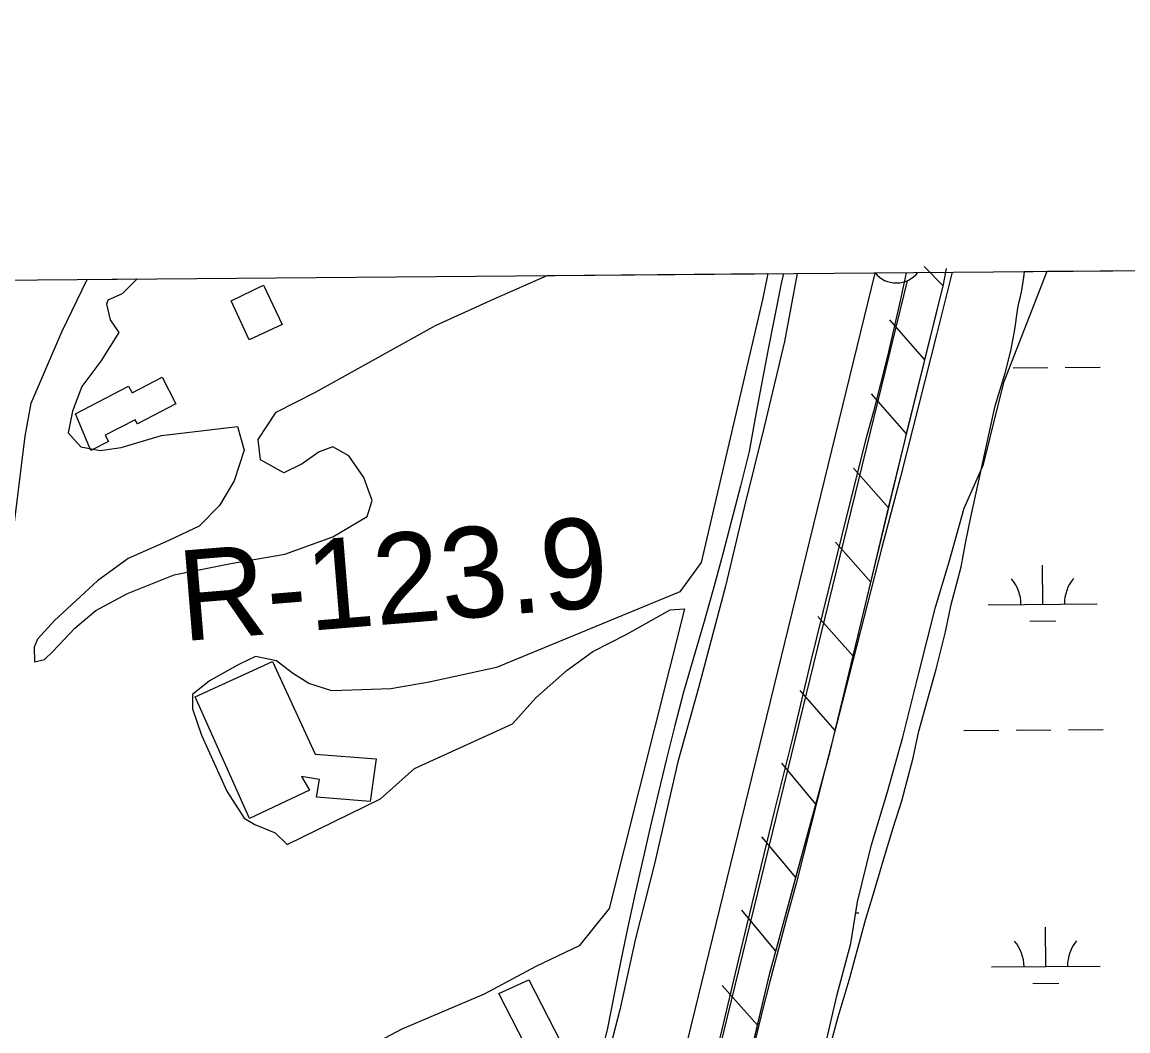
# Model space of a CAD drawing. Extents: x 3567028 to 3605064, y 510945 to 536587.
# Drawn here: x 3574682 to 3575698, y 533872 to 534798 of the extents above; entities that cross this region are included whole.
import ezdxf

# ---------------------------------------------------------------- set-up
doc = ezdxf.new("R2010")
doc.units = 0
for name, color, linetype in [('V-BLDG-OTLN', 7, 'Continuous'), ('V-FLOD-BASE', 7, 'Continuous'), ('V-GRID-FRAM', 7, 'Continuous'), ('V-LEVE-TOET', 7, 'Continuous'), ('V-RIVR-RANG-IDEN', 7, 'Continuous'), ('V-RRAP-FSHR', 7, 'Continuous'), ('V-SITE-VEGE', 7, 'Continuous'), ('V-SURV-LINE', 7, 'Continuous'), ('V-TOPO-SHOR', 7, 'Continuous'), ('V-WETL-SWMP', 7, 'Continuous')]:
    doc.layers.add(name, color=color, linetype=linetype)

msp = doc.modelspace()

# ---------------------------------------------------------------- linework, layer by layer
at = {"layer": 'V-BLDG-OTLN'}
for points in [[(3574874.162, 534542.454), (3574904.149, 534556.995), (3574921.025, 534520.903), (3574890.8310000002, 534506.786)], [(3574731.222, 534438.68), (3574780.088, 534464.14), (3574783.287, 534458.027), (3574810.785, 534472.306), (3574823.446, 534447.912), (3574788.1890000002, 534429.611), (3574786.225, 534433.402), (3574758.67, 534419.111), (3574761.586, 534413.4990000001), (3574745.548, 534405.178)], [(3574841.298, 534178.807), (3574912.3680000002, 534211.304), (3574951.431, 534126.218), (3575007.409, 534122.12), (3575001.915, 534082.715), (3574952.668, 534086.9230000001), (3574955.364, 534103.047), (3574939.035, 534105.7440000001), (3574946.213, 534093.157), (3574890.995, 534067.174)], [(3575120.199, 533906.402), (3575147.677, 533919.188), (3575183.103, 533849.871), (3575156.182, 533836.107)]]:
    msp.add_lwpolyline(points, close=True, dxfattribs=at)
at = {"layer": 'V-FLOD-BASE'}
msp.add_lwpolyline([(3575494.3409218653, 534568.5458403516), (3575494.278, 534568.24), (3575488.751, 534542.659), (3575482.969, 534517.134), (3575476.936, 534491.667), (3575470.649, 534466.262), (3575464.111, 534440.92), (3575457.3200000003, 534415.6460000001), (3575440.099, 534347.39), (3575423.151, 534279.063), (3575406.483, 534210.67), (3575390.089, 534142.209), (3575373.1040000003, 534073.785), (3575356.372, 534005.2980000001), (3575339.892, 533936.752), (3575323.666, 533868.144), (3575309.076, 533810.49), (3575294.684, 533752.786), (3575280.4960000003, 533695.032), (3575266.506, 533637.23), (3575252.719, 533579.38), (3575252.129, 533577.223)], dxfattribs=at)
at = {"layer": 'V-GRID-FRAM'}
msp.add_lwpolyline([(3571081.45, 534531.318), (3602744.09, 534798.429), (3602905.413, 516616.226), (3571226.9050000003, 516348.981), (3571081.45, 534531.318)], dxfattribs=at)
at = {"layer": 'V-LEVE-TOET'}
for points in [[(3575394.099627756, 534567.7001890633), (3575382.345, 534505.2930000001), (3575363.772, 534426.885), (3575345.536, 534352.725), (3575328.151, 534280.469), (3575303.466, 534187.349), (3575284.498, 534119.228), (3575262.957, 534025.514), (3575245.627, 533956.959), (3575231.223, 533891.651), (3575213.481, 533823.102)], [(3575536.510123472, 534568.9015863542), (3575522.09, 534511.4), (3575505.565, 534446.194), (3575488.876, 534381.03), (3575472.023, 534315.912), (3575445.575, 534213.176), (3575419.2970000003, 534110.397), (3575393.1950000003, 534007.573), (3575384.917, 533977.669), (3575376.8540000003, 533947.706), (3575369.006, 533917.685), (3575361.373, 533887.61), (3575353.958, 533857.48)]]:
    msp.add_lwpolyline(points, dxfattribs=at)
at = {"layer": 'V-RRAP-FSHR'}
for p, q in [((3575528.3009049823, 534556.2458612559), (3575510.700940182, 534573.9838257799)), ((3575511.3839388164, 534488.3189971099), (3575479.295002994, 534525.125923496)), ((3575494.5479724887, 534420.375132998), (3575462.459036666, 534457.1820593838)), ((3575478.1510052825, 534352.3242691), (3575445.7980699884, 534388.89919595)), ((3575461.8030379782, 534284.2604052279), (3575429.4511026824, 534320.8363320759)), ((3575445.4560706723, 534216.197541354), (3575413.103135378, 534252.772468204)), ((3575429.108103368, 534148.13467748), (3575396.7551680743, 534184.7096043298)), ((3575411.3091389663, 534080.4438128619), (3575380.0912014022, 534117.9917377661)), ((3575392.8851758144, 534012.9129479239), (3575361.6682382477, 534050.460872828)), ((3575374.46221266, 533945.382082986), (3575343.244275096, 533982.93000789)), ((3575357.7332461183, 533877.4212189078), (3575325.1953111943, 533913.832146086))]:
    msp.add_line(p, q, dxfattribs=at)
for points in [[(3575155.77265004, 532573.846826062), (3575140.8546798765, 532700.735572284), (3575135.5026905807, 532811.8853499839), (3575134.948691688, 532887.584198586), (3575141.241679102, 532954.5570646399), (3575155.175651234, 533020.4409328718), (3575188.9215837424, 533151.3956709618), (3575252.4544566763, 533426.1711214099), (3575322.163317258, 533725.956521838), (3575368.93722371, 533925.1321234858), (3575424.1831132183, 534127.630718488), (3575492.87197584, 534413.6131465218), (3575528.52690453, 534557.4998587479), (3575531.1608992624, 534572.1048295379)], [(3575528.220905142, 534556.262861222), (3575528.52690453, 534557.4998587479), (3575531.1608992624, 534572.1048295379)], [(3575511.3839388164, 534488.3189971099), (3575528.220905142, 534556.2638612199)], [(3575494.5479724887, 534420.375132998), (3575511.3839388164, 534488.319997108)], [(3575478.1510052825, 534352.3242691), (3575492.87197584, 534413.6131465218), (3575494.5479724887, 534420.3761329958)], [(3575461.8030379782, 534284.2604052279), (3575478.1510052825, 534352.3252690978)], [(3575445.4560706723, 534216.197541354), (3575461.8040379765, 534284.261405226)], [(3575429.108103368, 534148.13467748), (3575445.4560706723, 534216.1985413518)], [(3575411.3091389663, 534080.4438128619), (3575424.1831132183, 534127.630718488), (3575429.108103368, 534148.1356774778)], [(3575392.8851758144, 534012.9129479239), (3575411.310138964, 534080.44481286)], [(3575374.46221266, 533945.382082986), (3575392.8861758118, 534012.913947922)], [(3575357.7332461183, 533877.4212189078), (3575368.93722371, 533925.1321234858), (3575374.46221266, 533945.383082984)], [(3575341.730278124, 533809.2763551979), (3575357.7332461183, 533877.422218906)]]:
    msp.add_lwpolyline(points, dxfattribs=at)
at = {"layer": 'V-SITE-VEGE'}
for p, q in [((3575115.869, 534544.473), (3575164.6626896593, 534565.7646230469)), ((3575164.6626896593, 534565.7646230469), (3575367.295509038, 534567.4740653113)), ((3575367.295509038, 534567.4740653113), (3575362.668, 534545.0379999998)), ((3575600.3850000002, 534552.3639999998), (3575602.308, 534563.995)), ((3575602.308, 534563.995), (3575602.965628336, 534569.4622154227)), ((3575602.965628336, 534569.4622154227), (3575948.350644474, 534572.3759376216)), ((3574718.6950000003, 534514.111), (3574742.143585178, 534562.2001855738)), ((3574742.143585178, 534562.2001855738), (3574788.0881875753, 534562.5877814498)), ((3574788.0881875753, 534562.5877814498), (3574774.1380000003, 534549.052)), ((3574774.1380000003, 534549.0519999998), (3574761.09, 534543.0819999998)), ((3575061.821, 534519.9989999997), (3575115.869, 534544.4729999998)), ((3575362.668, 534545.0379999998), (3575305.916, 534302.199)), ((3575597.281, 534539.5819999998), (3575599.134, 534546.552)), ((3575599.134, 534546.552), (3575600.3850000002, 534552.3639999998)), ((3574761.09, 534543.0819999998), (3574759.8000000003, 534539.4)), ((3574759.8000000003, 534539.4), (3574763.286, 534525.1559999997)), ((3575594.02, 534516.311), (3575596.613, 534533.762)), ((3575596.613, 534533.762), (3575597.281, 534539.5819999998)), ((3574763.286, 534525.1559999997), (3574771.1240000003, 534513.3149999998)), ((3574690.551, 534448.5239999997), (3574718.6950000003, 534514.111)), ((3574771.1240000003, 534513.3149999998), (3574754.684, 534487.035)), ((3574951.685, 534458.7440000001), (3575061.821, 534519.9989999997)), ((3575590.2290000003, 534496.5479999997), (3575594.02, 534516.311)), ((3575585.265, 534476.215), (3575590.2290000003, 534496.5479999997)), ((3574754.684, 534487.035), (3574737.057, 534463.86)), ((3575576.074, 534446.0380000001), (3575585.265, 534476.215)), ((3574737.057, 534463.86), (3574728.6890000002, 534441.1579999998)), ((3574915.6180000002, 534440.1639999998), (3574951.685, 534458.7440000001)), ((3574685.157, 534418.3740000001), (3574690.551, 534448.5239999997)), ((3575564.828, 534395.483), (3575576.074, 534446.0380000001)), ((3574728.6890000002, 534441.1579999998), (3574724.6890000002, 534421.474)), ((3574899.197, 534415.1189999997), (3574915.6180000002, 534440.1639999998)), ((3574810.41, 534418.9369999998), (3574880.253, 534427.131)), ((3574880.253, 534427.131), (3574886.092, 534405.4469999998)), ((3574675.31, 534338.936), (3574685.157, 534418.3740000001)), ((3574724.6890000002, 534421.474), (3574736.213, 534408.343)), ((3574773.223, 534407.7789999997), (3574810.41, 534418.9369999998)), ((3574901.382, 534396.577), (3574899.197, 534415.1189999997)), ((3574736.213, 534408.343), (3574754.0530000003, 534404.988)), ((3574754.0530000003, 534404.988), (3574773.223, 534407.779)), ((3574886.092, 534405.4469999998), (3574877.026, 534377.2049999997)), ((3574955.169, 534403.78), (3574939.58, 534392.9109999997)), ((3574967.58, 534408.5269999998), (3574955.169, 534403.7799999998)), ((3574982.262, 534400.2839999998), (3574967.58, 534408.5269999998)), ((3574922.794, 534384.5279999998), (3574901.382, 534396.5769999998)), ((3574939.58, 534392.9109999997), (3574922.794, 534384.5279999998)), ((3574996.15, 534380.3279999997), (3574982.262, 534400.2839999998)), ((3575553.566, 534343.765), (3575564.828, 534395.483)), ((3574877.026, 534377.2049999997), (3574863.7260000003, 534354.578)), ((3575003.848, 534359.2339999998), (3574996.15, 534380.3279999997)), ((3574863.7260000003, 534354.578), (3574844.929, 534335.7390000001)), ((3574999.306, 534344.4959999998), (3575003.848, 534359.2339999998)), ((3574967.557, 534325.8529999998), (3574999.306, 534344.4959999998)), ((3575549.157, 534321.6749999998), (3575553.566, 534343.765)), ((3574844.929, 534335.7390000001), (3574816.966, 534322.5909999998)), ((3574816.966, 534322.5909999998), (3574779.694, 534305.8809999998)), ((3574923.507, 534309.866), (3574967.557, 534325.8529999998)), ((3575544.7290000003, 534298.4219999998), (3575549.157, 534321.6749999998)), ((3574874.021, 534301.361), (3574923.507, 534309.866)), ((3574779.694, 534305.8809999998), (3574751.6180000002, 534285.331)), ((3574822.039, 534291.0489999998), (3574874.021, 534301.361)), ((3575305.916, 534302.199), (3575286.38, 534275.3469999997)), ((3574779.205, 534273.807), (3574822.039, 534291.0489999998)), ((3575535.468, 534263.58), (3575544.7290000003, 534298.4219999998)), ((3574751.6180000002, 534285.331), (3574712.194, 534248.914)), ((3574749.972, 534258.21), (3574779.205, 534273.807)), ((3575286.38, 534275.3469999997), (3575118.122, 534205.7220000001)), ((3575290.781, 534259.8689999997), (3575221.491, 533984.505)), ((3575277.492, 534258.8239999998), (3575290.781, 534259.8689999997)), ((3575530.434, 534238.5859999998), (3575535.468, 534263.58)), ((3574712.194, 534248.914), (3574696.511, 534231.877)), ((3574730.596, 534241.8459999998), (3574749.972, 534258.21)), ((3575237.666, 534236.6029999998), (3575277.492, 534258.8239999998)), ((3574710.531, 534220.557), (3574730.596, 534241.8459999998)), ((3574696.511, 534231.877), (3574693.3140000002, 534224.52)), ((3575206.571, 534220.4180000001), (3575237.666, 534236.6029999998)), ((3575521.7630000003, 534204.319), (3575530.434, 534238.5859999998)), ((3574693.3140000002, 534224.52), (3574693.725, 534210.942)), ((3574703.0130000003, 534213.268), (3574710.531, 534220.557)), ((3575182.87, 534203.504), (3575206.571, 534220.4180000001)), ((3574693.725, 534210.942), (3574703.0130000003, 534213.268)), ((3574881.251, 534208.708), (3574854.491, 534193.6899999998)), ((3574896.785, 534215.8739999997), (3574881.251, 534208.708)), ((3574915.85, 534211.882), (3574896.785, 534215.8740000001)), ((3574930.485, 534200.554), (3574915.85, 534211.882)), ((3574945.765, 534191.066), (3574930.485, 534200.554)), ((3575118.122, 534205.7220000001), (3575056.224, 534192.4709999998)), ((3575154.102, 534178.0259999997), (3575182.87, 534203.5039999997)), ((3575505.7600000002, 534147.4229999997), (3575521.7630000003, 534204.319)), ((3574854.491, 534193.6899999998), (3574838.873, 534180.9689999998)), ((3574966.642, 534184.58), (3574945.765, 534191.066)), ((3575056.224, 534192.4709999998), (3575020.963, 534186.2229999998)), ((3574838.873, 534180.9689999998), (3574838.677, 534168.018)), ((3574994.419, 534185.3909999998), (3574966.642, 534184.5799999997)), ((3575020.963, 534186.2229999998), (3574994.419, 534185.3909999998)), ((3575132.7630000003, 534154.292), (3575154.102, 534178.0259999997)), ((3574838.677, 534168.018), (3574846.947, 534143.829)), ((3575042.676, 534113.0879999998), (3575132.7630000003, 534154.2919999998)), ((3575500.734, 534123.011), (3575505.7600000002, 534147.4229999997)), ((3574846.947, 534143.829), (3574870.224, 534092.2660000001)), ((3575490.238, 534083.5239999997), (3575500.734, 534123.011)), ((3575011.403, 534085.184), (3575042.676, 534113.0879999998)), ((3574870.224, 534092.2660000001), (3574886.1410000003, 534067.475)), ((3574925.627, 534043.301), (3575011.403, 534085.184)), ((3575482.287, 534058.573), (3575490.238, 534083.5239999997)), ((3574886.1410000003, 534067.475), (3574896.129, 534061.7639999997)), ((3574896.129, 534061.7639999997), (3574914.68, 534053.955)), ((3575474.321, 534032.457), (3575482.287, 534058.573)), ((3574914.68, 534053.955), (3574925.627, 534043.301)), ((3575463.884, 533997.051), (3575474.321, 534032.457)), ((3575457.144, 533974.996), (3575463.884, 533997.051)), ((3575221.491, 533984.505), (3575193.825, 533950.3789999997)), ((3575441.733, 533918.674), (3575457.144, 533974.996)), ((3575193.825, 533950.3789999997), (3575154.048, 533931.238)), ((3575154.048, 533931.238), (3575106.774, 533906.044)), ((3575431.9050000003, 533885.007), (3575441.733, 533918.674)), ((3575106.774, 533906.044), (3575031.017, 533873.8799999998)), ((3575425.738, 533862.3619999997), (3575431.9050000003, 533885.007)), ((3575031.017, 533873.8799999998), (3574876.768, 533792.3159999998))]:
    msp.add_line(p, q, dxfattribs=at)
at = {"layer": 'V-SURV-LINE'}
for points in [[(3575084.630423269, 533008.6711372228), (3575465.885403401, 534568.0683542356)], [(3575495.030641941, 534560.9581294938), (3575113.775602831, 533001.5606712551)]]:
    msp.add_lwpolyline(points, dxfattribs=at)
msp.add_arc((3575485.20279, 534583.92135), 25, 218.6595530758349, 322.30713636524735, dxfattribs=at)
at = {"layer": 'V-TOPO-SHOR'}
msp.add_lwpolyline([(3575381.5162008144, 534567.5940332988), (3575379.566, 534558.336), (3575373.285, 534527.552), (3575367.198, 534496.73), (3575361.308, 534465.871), (3575355.612, 534434.975), (3575350.114, 534404.042), (3575342.116, 534372.341), (3575333.9080000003, 534340.693), (3575325.488, 534309.103), (3575316.8540000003, 534277.567), (3575308.011, 534246.0920000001), (3575298.957, 534214.675), (3575289.691, 534183.323), (3575281.801, 534152.6950000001), (3575274.112, 534122.014), (3575266.631, 534091.283), (3575259.35, 534060.504), (3575252.2770000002, 534029.676), (3575245.4050000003, 533998.802), (3575238.741, 533967.883), (3575232.282, 533936.922), (3575226.0270000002, 533905.917), (3575219.98, 533874.871), (3575202.2460000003, 533802.507)], dxfattribs=at)
at = {"layer": 'V-WETL-SWMP'}
for p, q in [((3575584.2839216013, 534468.4201125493), (3575623.8670928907, 534569.6385434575)), ((3575623.8670928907, 534569.6385434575), (3575948.34858709, 534572.375920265)), ((3575592.404077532, 534481.003021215), (3575624.4025755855, 534481.2729675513)), ((3575640.4018246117, 534481.4079407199), (3575672.4003226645, 534481.6778870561)), ((3575577.3837343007, 534441.7882403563), (3575584.2839216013, 534468.4201125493)), ((3575565.210286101, 534392.3313271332), (3575577.3837343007, 534441.7882403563)), ((3575547.4554410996, 534352.1483515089), (3575565.210286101, 534392.3313271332)), ((3575533.652999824, 534302.9195966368), (3575547.4554410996, 534352.1483515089)), ((3575521.1869160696, 534261.2297407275), (3575533.6529998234, 534302.9195966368)), ((3575619.644261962, 534263.9821494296), (3575619.340447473, 534299.9808583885)), ((3575505.985255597, 534200.7848505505), (3575521.1869160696, 534261.2297407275)), ((3575569.646608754, 534263.5603582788), (3575669.64191517, 534264.4039405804)), ((3575607.775051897, 534248.4504729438), (3575631.7739254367, 534248.6529326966)), ((3575491.012650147, 534141.9721262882), (3575505.985255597, 534200.7848505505)), ((3575547.21387171, 534147.9350321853), (3575579.2123697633, 534148.2049785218)), ((3575595.21161879, 534148.3399516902), (3575627.2101168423, 534148.6098980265)), ((3575643.2093658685, 534148.744871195), (3575675.207863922, 534149.0148175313)), ((3575477.1915859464, 534091.7219589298), (3575491.012650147, 534141.9721262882)), ((3575462.3728051, 534042.9159933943), (3575477.1915859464, 534091.7219589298)), ((3575449.5422403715, 533990.6087473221), (3575462.3728051, 534042.9159933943)), ((3575443.2604356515, 533952.5032498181), (3575449.5422403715, 533990.6087473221)), ((3575447.890659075, 533980.590236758), (3575450.7156175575, 533980.6140687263)), ((3575622.451803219, 533931.3190799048), (3575622.1479887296, 533967.3177888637)), ((3575430.7173010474, 533905.7072286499), (3575443.260435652, 533952.5032498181)), ((3575572.4541500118, 533930.897288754), (3575672.4494564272, 533931.7408710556)), ((3575610.5825931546, 533915.787403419), (3575634.581466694, 533915.9898631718)), ((3575419.34604469, 533855.4197165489), (3575430.7173010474, 533905.7072286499))]:
    msp.add_line(p, q, dxfattribs=at)
for centre, radius, start, end in [((3575564.399911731, 534263.9909159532), 35.24628790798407, 359.71151968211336, 41.2551780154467), ((3575674.8805981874, 534264.9229552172), 35.246287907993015, 139.7115338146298, 181.25519214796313), ((3575567.2074529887, 533931.3278464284), 35.24628790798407, 359.71151968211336, 41.2551780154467), ((3575677.688139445, 533932.2598856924), 35.246287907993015, 139.7115338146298, 181.25519214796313)]:
    msp.add_arc(centre, radius, start, end, dxfattribs=at)

# ---------------------------------------------------------------- texts
at = {"layer": 'V-RIVR-RANG-IDEN'}
msp.add_text('R-123.9', height=82.999998, rotation=4.69161627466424, dxfattribs=at).set_placement((3574829.65, 534229.9400000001))

doc.saveas('drawing.dxf')
